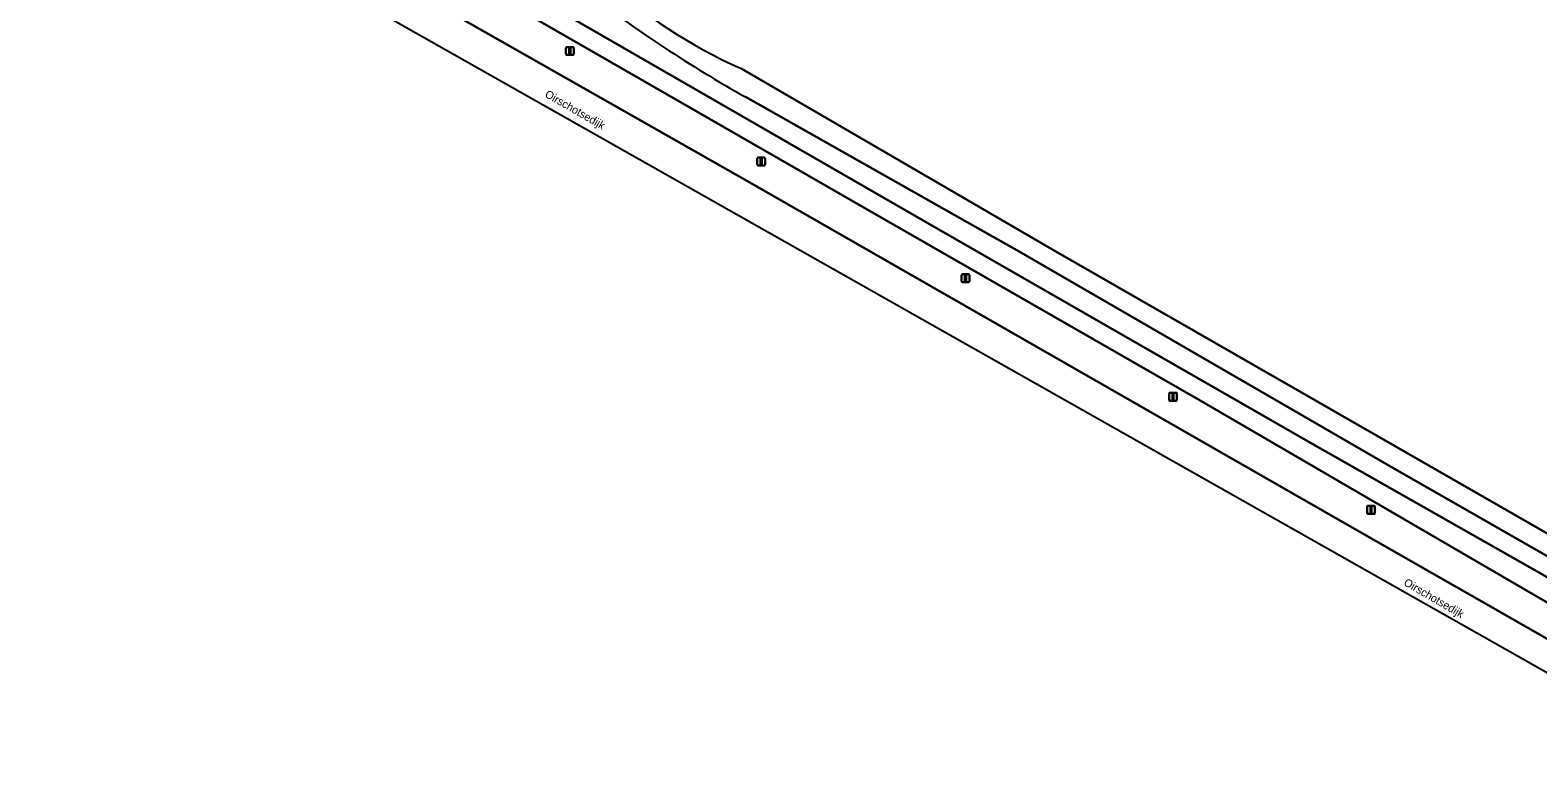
# Model space of a CAD drawing. Extents: x 157132 to 159279, y 384991 to 386650.
# Drawn here: x 157211.6 to 157400.4, y 385934.6 to 386027.8 of the extents above; entities that cross this region are included whole.
import ezdxf

# ---------------------------------------------------------------- set-up
doc = ezdxf.new("R2010")
doc.units = 0
for name, color, linetype in [('IMGEO_Groenvoorziening', 7, 'Continuous'), ('IMGEO_Lichtmast', 7, 'Continuous'), ('IMGEO_Loofbos', 7, 'Continuous'), ('IMGEO_Openbare_ruimte_label', 7, 'Continuous'), ('IMGEO_Rijbaan_lokaal_gesloten', 7, 'Continuous'), ('IMGEO_Voetpad_open', 7, 'Continuous'), ('IMGEO_Waterloop', 7, 'Continuous')]:
    doc.layers.add(name, color=color, linetype=linetype)

msp = doc.modelspace()

# ---------------------------------------------------------------- linework, layer by layer
at = {"layer": 'IMGEO_Groenvoorziening'}
for points in [[(157211.81, 386074.46), (157213.46, 386068.27), (157211.58, 386069.38), (157211.87, 386068.54), (157226.55, 386059.05), (157238.01, 386052.55), (157275.38, 386031.65), (157325.1, 386002.94), (157371.95, 385976.04), (157409.6, 385954.65), (157433.37, 385941.16), (157433.81, 385941.48), (157436.42, 385943.53), (157438.46, 385945.46), (157516.04, 386019.65)], [(157218.68, 386055.75), (157223.15, 386053.17), (157245.84, 386040.45), (157301.73, 386008.65), (157378.01, 385964.93), (157425.7, 385937.7), (157430.25, 385939.57), (157430.82, 385939.8), (157410.95, 385950.56), (157358.1, 385981.34), (157315.93, 386005.59), (157238.95, 386049.87), (157225.52, 386057.6), (157213.47, 386063.29)], [(157430.99, 385945.03), (157382.24, 385972.9), (157335.45, 386000), (157327.31, 386004.6), (157301.16, 386019.38)]]:
    msp.add_lwpolyline(points, dxfattribs=at)
msp.add_arc((157385.37, 386169), 171.69, 232.6643, 240.6286, dxfattribs=at)
at = {"layer": 'IMGEO_Lichtmast'}
for p, q in [((157278.68, 386024.74), (157278.68, 386025.54)), ((157278.68, 386025.54), (157278.68, 386024.74)), ((157278.78, 386025.64), (157279.57, 386025.64)), ((157279.57, 386025.64), (157278.78, 386025.64)), ((157279.67, 386025.54), (157279.67, 386024.74)), ((157279.67, 386024.74), (157279.67, 386025.54)), ((157279.57, 386024.64), (157278.78, 386024.64)), ((157278.78, 386024.64), (157279.57, 386024.64)), ((157302.64, 386010.91), (157302.64, 386011.7)), ((157302.64, 386011.7), (157302.64, 386010.91)), ((157302.74, 386011.8), (157303.53, 386011.8)), ((157303.53, 386011.8), (157302.74, 386011.8)), ((157303.63, 386011.7), (157303.63, 386010.91)), ((157303.63, 386010.91), (157303.63, 386011.7)), ((157303.53, 386010.81), (157302.74, 386010.81)), ((157302.74, 386010.81), (157303.53, 386010.81)), ((157328.23, 385996.27), (157328.23, 385997.07)), ((157328.23, 385997.07), (157328.23, 385996.27)), ((157328.33, 385997.17), (157329.12, 385997.17)), ((157329.12, 385997.17), (157328.33, 385997.17)), ((157329.22, 385997.07), (157329.22, 385996.27)), ((157329.22, 385996.27), (157329.22, 385997.07)), ((157329.12, 385996.17), (157328.33, 385996.17)), ((157328.33, 385996.17), (157329.12, 385996.17)), ((157354.22, 385981.42), (157354.22, 385982.22)), ((157354.22, 385982.22), (157354.22, 385981.42)), ((157354.32, 385982.32), (157355.11, 385982.32)), ((157355.11, 385982.32), (157354.32, 385982.32)), ((157355.21, 385982.22), (157355.21, 385981.42)), ((157355.21, 385981.42), (157355.21, 385982.22)), ((157355.11, 385981.32), (157354.32, 385981.32)), ((157354.32, 385981.32), (157355.11, 385981.32)), ((157379.02, 385967.25), (157379.02, 385968.05)), ((157379.02, 385968.05), (157379.02, 385967.25)), ((157379.12, 385968.15), (157379.91, 385968.15)), ((157379.91, 385968.15), (157379.12, 385968.15)), ((157379.91, 385967.15), (157379.12, 385967.15)), ((157379.12, 385967.15), (157379.91, 385967.15)), ((157380.01, 385968.05), (157380.01, 385967.25)), ((157380.01, 385967.25), (157380.01, 385968.05))]:
    msp.add_line(p, q, dxfattribs=at)
for points in [[(157279.1, 386025.51), (157279.25, 386025.51), (157279.25, 386024.76), (157279.1, 386024.76), (157279.1, 386025.51)], [(157303.06, 386011.68), (157303.21, 386011.68), (157303.21, 386010.93), (157303.06, 386010.93), (157303.06, 386011.68)], [(157328.65, 385997.04), (157328.8, 385997.04), (157328.8, 385996.29), (157328.65, 385996.29), (157328.65, 385997.04)], [(157354.64, 385982.19), (157354.79, 385982.19), (157354.79, 385981.44), (157354.64, 385981.44), (157354.64, 385982.19)], [(157379.44, 385968.02), (157379.59, 385968.02), (157379.59, 385967.27), (157379.44, 385967.27), (157379.44, 385968.02)]]:
    msp.add_lwpolyline(points, dxfattribs=at)
for centre, start, end in [((157278.78, 386025.54), 90, 180), ((157278.78, 386025.54), 90, 180), ((157279.57, 386025.54), 0, 90), ((157279.57, 386025.54), 360, 90), ((157278.78, 386024.74), 180, 270), ((157278.78, 386024.74), 180, 270), ((157279.57, 386024.74), 270, 0), ((157279.57, 386024.74), 270, 0), ((157302.74, 386011.7), 90, 180), ((157302.74, 386011.7), 90, 180), ((157303.53, 386011.7), 0, 90), ((157303.53, 386011.7), 360, 90), ((157302.74, 386010.91), 180, 270), ((157302.74, 386010.91), 180, 270), ((157303.53, 386010.91), 270, 0), ((157303.53, 386010.91), 270, 0), ((157328.33, 385997.07), 90, 180), ((157328.33, 385997.07), 90, 180), ((157329.12, 385997.07), 0, 90), ((157329.12, 385997.07), 360, 90), ((157328.33, 385996.27), 180, 270), ((157328.33, 385996.27), 180, 270), ((157329.12, 385996.27), 270, 0), ((157329.12, 385996.27), 270, 0), ((157354.32, 385982.22), 90, 180), ((157354.32, 385982.22), 90, 180), ((157355.11, 385982.22), 0, 90), ((157355.11, 385982.22), 360, 90), ((157354.32, 385981.42), 180, 270), ((157354.32, 385981.42), 180, 270), ((157355.11, 385981.42), 270, 0), ((157355.11, 385981.42), 270, 0), ((157379.12, 385968.05), 90, 180), ((157379.12, 385968.05), 90, 180), ((157379.12, 385967.25), 180, 270), ((157379.12, 385967.25), 180, 270), ((157379.91, 385968.05), 0, 90), ((157379.91, 385968.05), 360, 90), ((157379.91, 385967.25), 270, 0), ((157379.91, 385967.25), 270, 0)]:
    msp.add_arc(centre, 0.1, start, end, dxfattribs=at)
at = {"layer": 'IMGEO_Loofbos'}
msp.add_lwpolyline([(157300.64, 386022.93), (157328.54, 386006.7), (157340.05, 386000), (157430.56, 385948.06)], dxfattribs=at)
msp.add_arc((157328.46, 386084.88), 67.91, 228.1345, 245.8077, dxfattribs=at)
at = {"layer": 'IMGEO_Rijbaan_lokaal_gesloten'}
msp.add_lwpolyline([(157424, 385934.57), (157425.7, 385937.7), (157378.01, 385964.93), (157301.73, 386008.65), (157245.84, 386040.45), (157243.66, 386036.66)], close=True, dxfattribs=at)
at = {"layer": 'IMGEO_Voetpad_open'}
msp.add_lwpolyline([(157211.87, 386068.54), (157212.53, 386065.94), (157213.47, 386063.29), (157225.52, 386057.6), (157238.95, 386049.87), (157315.93, 386005.59), (157358.1, 385981.34), (157410.95, 385950.56), (157430.82, 385939.8), (157432.43, 385940.47), (157433.37, 385941.16), (157409.6, 385954.65), (157371.95, 385976.04), (157325.1, 386002.94), (157275.38, 386031.65), (157238.01, 386052.55), (157226.55, 386059.05)], close=True, dxfattribs=at)
at = {"layer": 'IMGEO_Waterloop'}
for points in [[(157430.56, 385948.06), (157340.05, 386000), (157328.54, 386006.7), (157300.64, 386022.93)], [(157301.16, 386019.38), (157327.31, 386004.6), (157335.45, 386000), (157382.24, 385972.9), (157430.99, 385945.03)]]:
    msp.add_lwpolyline(points, dxfattribs=at)
for centre, radius, start, end in [((157385.37, 386169), 171.69, 232.6643, 240.6286), ((157328.46, 386084.88), 67.91, 228.1345, 245.8077)]:
    msp.add_arc(centre, radius, start, end, dxfattribs=at)

# ---------------------------------------------------------------- texts
at = {"layer": 'IMGEO_Openbare_ruimte_label'}
for rotation, p in [(330.0775, (157275.95, 386019.45)), (329.8714, (157383.52, 385958.27))]:
    msp.add_text('Oirschotsedijk', height=1, rotation=rotation, dxfattribs=at).set_placement(p)

doc.saveas('drawing.dxf')
